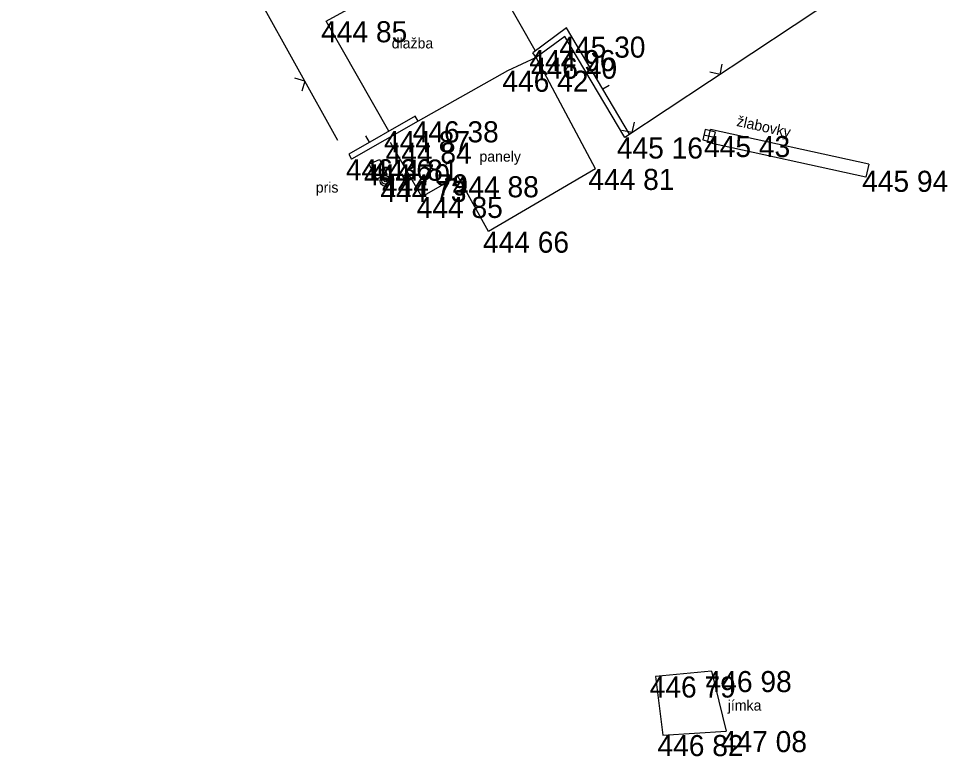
# Model space of a CAD drawing. Extents: x -554123 to -553118, y -1076825 to -1073672.
# Drawn here: x -553878.9 to -553834.78, y -1073760.48 to -1073725.46 of the extents above; entities that cross this region are included whole.
import ezdxf

# ---------------------------------------------------------------- set-up
doc = ezdxf.new("R2010")
doc.units = 0
for name, color, linetype in [('1', 7, 'Continuous'), ('12', 7, 'Continuous'), ('17', 7, 'Continuous'), ('18', 7, 'Continuous'), ('20', 7, 'Continuous'), ('40', 7, 'Continuous'), ('52', 7, 'Continuous'), ('6', 7, 'Continuous')]:
    doc.layers.add(name, color=color, linetype=linetype)

# ---------------------------------------------------------------- blocks, each defined once
blk = doc.blocks.new('POINT_DISPLAY')
blk.add_line((0, 0), (0, 0))
blk = doc.blocks.new('VP')
at = {"layer": '40'}
blk.add_line((-0.25, 0), (0.25, 0), dxfattribs=at)
blk.add_lwpolyline([(-0.25, -0.25), (0.25, -0.25), (0.25, 0.25), (-0.25, 0.25)], close=True, dxfattribs=at)
blk = doc.blocks.new('SLB')
at = {"layer": '20'}
for radius in [0.25, 0.158, 0.05]:
    blk.add_circle((0, 0), radius, dxfattribs=at)

msp = doc.modelspace()

# ---------------------------------------------------------------- linework, layer by layer
at = {"layer": '12'}
for p, q in [((-553878.9, -1073703.95), (-553863.75, -1073731.22)), ((-553835.15, -1073721.21), (-553850.11, -1073731.1)), ((-553852.877, -1073725.901), (-553854.476, -1073727.085)), ((-553849.876, -1073730.945), (-553852.877, -1073725.901)), ((-553852.96, -1073726.31), (-553854.31, -1073727.31)), ((-553850.11, -1073731.1), (-553852.96, -1073726.31)), ((-553854.31, -1073727.31), (-553855.67, -1073727.93)), ((-553854.31, -1073727.31), (-553854.476, -1073727.085)), ((-553845.577, -1073728.103), (-553845.477, -1073727.613)), ((-553855.67, -1073727.93), (-553859.92, -1073730.33)), ((-553845.577, -1073728.103), (-553846.068, -1073728.003)), ((-553865.302, -1073728.426), (-553865.783, -1073728.289)), ((-553865.302, -1073728.426), (-553865.44, -1073728.908)), ((-553851.154, -1073728.797), (-553850.853, -1073728.618)), ((-553860.058, -1073730.086), (-553863.218, -1073731.886)), ((-553859.92, -1073730.33), (-553863.08, -1073732.13)), ((-553859.92, -1073730.33), (-553860.058, -1073730.086)), ((-553849.748, -1073730.861), (-553849.648, -1073730.37)), ((-553849.748, -1073730.861), (-553850.239, -1073730.761)), ((-553862.23, -1073731.323), (-553862.404, -1073731.019)), ((-553863.218, -1073731.886), (-553863.08, -1073732.13))]:
    msp.add_line(p, q, dxfattribs=at)
at = {"layer": '17'}
for p, q in [((-553857.34, -1073721.73), (-553854.38, -1073726.95)), ((-553864.29, -1073725.58), (-553861.4, -1073723.96)), ((-553861.31, -1073730.8), (-553864.29, -1073725.58))]:
    msp.add_line(p, q, dxfattribs=at)
at = {"layer": '18'}
for p, q in [((-553851.49, -1073732.59), (-553854.31, -1073727.31)), ((-553846.168, -1073731.342), (-553846.031, -1073730.717)), ((-553838.511, -1073732.367), (-553846.031, -1073730.717)), ((-553859.75, -1073733.92), (-553861.24, -1073731.34)), ((-553838.648, -1073732.992), (-553846.168, -1073731.342)), ((-553862.26, -1073732.37), (-553861.75, -1073732.15)), ((-553861.75, -1073732.15), (-553861.39, -1073732.85)), ((-553862.26, -1073732.37), (-553861.9, -1073733.07)), ((-553851.49, -1073732.59), (-553856.58, -1073735.57)), ((-553838.511, -1073732.367), (-553838.648, -1073732.992)), ((-553861.9, -1073733.07), (-553861.39, -1073732.85)), ((-553858.04, -1073732.94), (-553859.75, -1073733.92)), ((-553856.58, -1073735.57), (-553858.04, -1073732.94)), ((-553845.99, -1073756.43), (-553848.65, -1073756.69)), ((-553845.99, -1073756.43), (-553845.29, -1073759.28)), ((-553848.65, -1073756.69), (-553848.29, -1073759.47)), ((-553848.29, -1073759.47), (-553845.29, -1073759.28))]:
    msp.add_line(p, q, dxfattribs=at)

# ---------------------------------------------------------------- block references
at = {"layer": '1'}
for p in [(-553864.29, -1073725.58), (-553852.96, -1073726.31), (-553854.38, -1073726.95), (-553854.31, -1073727.31), (-553855.67, -1073727.93), (-553859.92, -1073730.33), (-553861.31, -1073730.8), (-553850.11, -1073731.1), (-553846.1, -1073731.03), (-553861.24, -1073731.34), (-553863.08, -1073732.13), (-553861.75, -1073732.15), (-553862.26, -1073732.37), (-553851.49, -1073732.59), (-553861.39, -1073732.85), (-553858.04, -1073732.94), (-553838.58, -1073732.68), (-553861.48, -1073733.16), (-553859.75, -1073733.92), (-553856.58, -1073735.57), (-553845.99, -1073756.43), (-553848.65, -1073756.69), (-553848.29, -1073759.47), (-553845.29, -1073759.28)]:
    msp.add_blockref('POINT_DISPLAY', p, dxfattribs=at)
at = {"layer": '20'}
msp.add_blockref('SLB', (-553861.48, -1073733.16), dxfattribs=at)
at = {"layer": '40', "xscale": 0.9999999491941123, "yscale": 0.9999999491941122, "rotation": -13.467371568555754}
msp.add_blockref('VP', (-553846.1, -1073731.03), dxfattribs=at)

# ---------------------------------------------------------------- texts
at = {"layer": '52'}
for s, p in [('dlažba', (-553861.174, -1073726.872)), ('panely', (-553857.009, -1073732.249)), ('pris', (-553864.784, -1073733.718)), ('jímka', (-553845.212, -1073758.309))]:
    msp.add_text(s, height=0.5, dxfattribs=at).set_placement(p)
msp.add_text('žlabovky', height=0.5, rotation=347.6246, dxfattribs=at).set_placement((-553844.825, -1073730.547))
at = {"layer": '6'}
for s, p in [('444 85 ', (-553864.528, -1073726.58)), ('445 30 ', (-553853.212, -1073727.31)), ('444 96 ', (-553854.642, -1073727.95)), ('446 40 ', (-553854.562, -1073728.31)), ('446 42 ', (-553855.92, -1073728.93)), ('446 38 ', (-553860.182, -1073731.33)), ('444 87 ', (-553861.546, -1073731.8)), ('445 16 ', (-553850.481, -1073732.1)), ('445 43 ', (-553846.338, -1073732.03)), ('444 84 ', (-553861.466, -1073732.34)), ('446 36 ', (-553863.354, -1073733.13)), ('444 81 ', (-553862.095, -1073733.15)), ('444 70 ', (-553862.498, -1073733.37)), ('444 81 ', (-553851.835, -1073733.59)), ('444 79 ', (-553861.638, -1073733.85)), ('444 88 ', (-553858.278, -1073733.94)), ('445 94 ', (-553838.83, -1073733.68)), ('444 73 ', (-553861.716, -1073734.16)), ('444 85 ', (-553859.988, -1073734.92)), ('444 66 ', (-553856.842, -1073736.57)), ('446 98 ', (-553846.264, -1073757.43)), ('446 79 ', (-553848.922, -1073757.69)), ('446 82 ', (-553848.552, -1073760.47)), ('447 08 ', (-553845.54, -1073760.28))]:
    msp.add_text(s, height=1, dxfattribs=at).set_placement(p)

doc.saveas('drawing.dxf')
